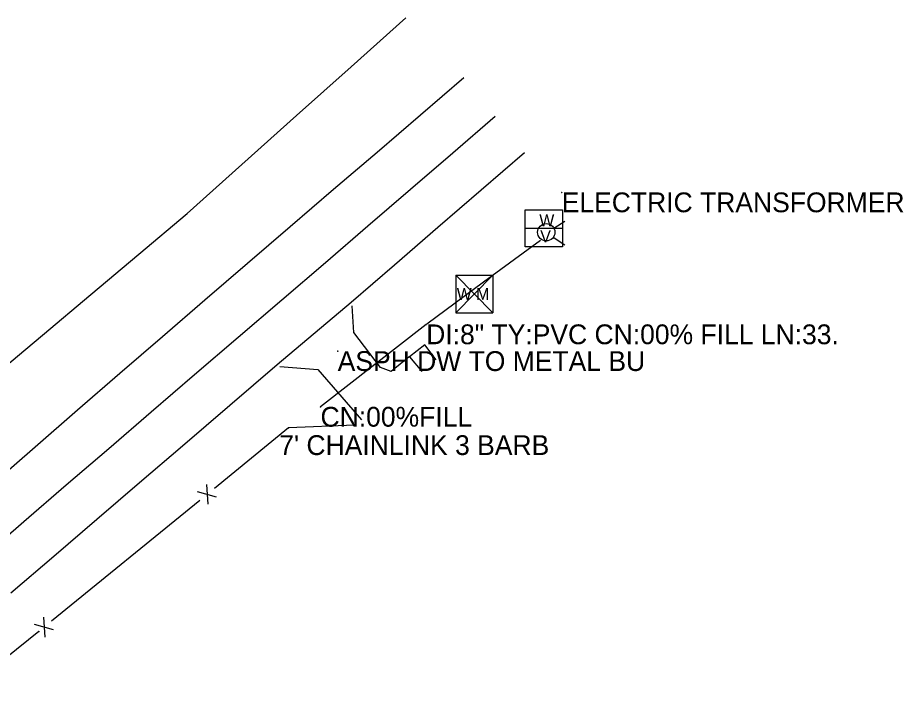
# Model space of a CAD drawing. Extents: x 1707085 to 1720058, y 548761 to 560063.
# Drawn here: x 1712693.8 to 1712917.4, y 549775.1 to 549943.4 of the extents above; entities that cross this region are included whole.
import ezdxf

# ---------------------------------------------------------------- set-up
doc = ezdxf.new("R2010")
doc.units = 0
for name, color, linetype in [('3', 7, 'Continuous'), ('R_Contours', 7, 'Continuous'), ('R_Water Annot', 7, 'Continuous'), ('S_DRG_PT_SYM', 7, 'Continuous'), ('S_DRIVEWAY', 7, 'Continuous'), ('S_EDGE_CONCRETE', 7, 'Continuous'), ('S_EDGE_PAVEMENT', 7, 'Continuous'), ('S_MISC_STRUCTURES_ANNOT', 7, 'Continuous'), ('S_MSC_PT_SYM', 7, 'Continuous'), ('S_PAVEMENT_CROWN', 7, 'Continuous'), ('S_SIDE_DRAIN_ANNOT', 7, 'Continuous'), ('S_SURVEY_TEXT_ANNOT', 7, 'Continuous')]:
    doc.layers.add(name, color=color, linetype=linetype)

msp = doc.modelspace()

# ---------------------------------------------------------------- linework, layer by layer
for points in [[(1712687.84, 549853.05), (1712700.01, 549863.27), (1712712.19, 549873.5), (1712724.37, 549883.72), (1712736.55, 549893.95), (1712750.36, 549906.32), (1712764.17, 549918.7), (1712777.99, 549931.07), (1712791.8, 549943.44)], [(1712825.79, 549887.17), (1712811.41, 549876.6), (1712797.03, 549866.03)]]:
    msp.add_lwpolyline(points)
at = {"layer": '3'}
msp.add_line((1712796.9, 549865.96), (1712770.22, 549845.13), dxfattribs=at)
at = {"layer": 'R_Contours'}
for p, q in [((1712778.87, 549840.55), (1712762.15, 549839.8)), ((1712741.39, 549825.52), (1712741.76, 549820.53)), ((1712743.98, 549822.35), (1712739.17, 549823.71)), ((1712700.24, 549791.98), (1712700.61, 549786.99)), ((1712702.83, 549788.81), (1712698.02, 549790.17))]:
    msp.add_line(p, q, dxfattribs=at)
for points in [[(1712778.87, 549840.55), (1712762.15, 549839.8)], [(1712762.15, 549839.8), (1712743.45, 549824.55)], [(1712739.71, 549821.5), (1712702.3, 549791.01)], [(1712699.09, 549788.39), (1712682.55, 549775.05)]]:
    msp.add_lwpolyline(points, dxfattribs=at)
at = {"layer": 'R_Water Annot'}
for p, q in [((1712821.91, 549894.93), (1712831.32, 549894.93)), ((1712821.91, 549885.52), (1712821.91, 549894.93)), ((1712831.32, 549894.93), (1712831.32, 549885.52)), ((1712829.12, 549890.3), (1712831.94, 549892.03)), ((1712821.91, 549890.24), (1712831.32, 549890.24)), ((1712828.99, 549887.99), (1712831.9, 549886.06)), ((1712831.32, 549885.52), (1712821.91, 549885.52)), ((1712804.42, 549878.41), (1712813.76, 549878.41)), ((1712804.42, 549878.41), (1712804.42, 549868.91)), ((1712804.42, 549878.41), (1712813.76, 549868.91)), ((1712813.76, 549878.41), (1712804.42, 549868.91)), ((1712813.76, 549878.41), (1712813.76, 549868.91)), ((1712804.42, 549868.91), (1712813.76, 549868.91))]:
    msp.add_line(p, q, dxfattribs=at)
msp.add_circle((1712827.21, 549889.24), 2.18, dxfattribs=at)
at = {"layer": 'S_DRG_PT_SYM'}
for points in [[(1712796.9, 549865.96), (1712796.9, 549866.01), (1712796.9, 549865.96), (1712796.85, 549865.96), (1712796.9, 549865.96), (1712796.9, 549865.91), (1712796.9, 549865.96), (1712796.95, 549865.96)], [(1712770.22, 549845.13), (1712770.22, 549845.18), (1712770.22, 549845.13), (1712770.17, 549845.13), (1712770.22, 549845.13), (1712770.22, 549845.08), (1712770.22, 549845.13), (1712770.27, 549845.13)]]:
    msp.add_lwpolyline(points, dxfattribs=at)
at = {"layer": 'S_DRIVEWAY'}
for points in [[(1712792.59, 549857.74), (1712788.04, 549854.08), (1712785.35, 549855.11), (1712778.67, 549863.91), (1712778.22, 549870.69)], [(1712759.92, 549855.36), (1712769.53, 549854.6), (1712780.56, 549841.85)]]:
    msp.add_lwpolyline(points, dxfattribs=at)
at = {"layer": 'S_EDGE_CONCRETE'}
msp.add_lwpolyline([(1712799.39, 549857.03), (1712796.55, 549860.79), (1712792.72, 549857.76), (1712795.77, 549854.04)], dxfattribs=at)
at = {"layer": 'S_EDGE_PAVEMENT'}
for points in [[(1712806.42, 549928.23), (1712795.45, 549918.82), (1712784.48, 549909.41), (1712773.51, 549900.01), (1712762.54, 549890.6), (1712751.79, 549881.34), (1712741.03, 549872.08), (1712730.28, 549862.81), (1712719.53, 549853.55), (1712708.83, 549844.26), (1712698.14, 549834.96), (1712687.44, 549825.67)], [(1712821.74, 549909.31), (1712810.79, 549899.87), (1712799.83, 549890.42), (1712788.88, 549880.97), (1712777.92, 549871.52), (1712759.29, 549855.72), (1712747.34, 549845.46), (1712735.4, 549835.21), (1712724.55, 549825.93), (1712713.71, 549816.65), (1712702.87, 549807.37), (1712692.02, 549798.1)]]:
    msp.add_lwpolyline(points, dxfattribs=at)
at = {"layer": 'S_MSC_PT_SYM'}
for points in [[(1712831.12, 549899.3), (1712831.12, 549899.35), (1712831.12, 549899.3), (1712831.07, 549899.3), (1712831.12, 549899.3), (1712831.12, 549899.25), (1712831.12, 549899.3), (1712831.17, 549899.3)], [(1712774.55, 549859.2), (1712774.55, 549859.25), (1712774.55, 549859.2), (1712774.5, 549859.2), (1712774.55, 549859.2), (1712774.55, 549859.15), (1712774.55, 549859.2), (1712774.6, 549859.2)], [(1712778.87, 549840.55), (1712778.87, 549840.6), (1712778.87, 549840.55), (1712778.82, 549840.55), (1712778.87, 549840.55), (1712778.87, 549840.5), (1712778.87, 549840.55), (1712778.92, 549840.55)], [(1712759.81, 549837.97), (1712759.81, 549838.02), (1712759.81, 549837.97), (1712759.76, 549837.97), (1712759.81, 549837.97), (1712759.81, 549837.92), (1712759.81, 549837.97), (1712759.86, 549837.97)], [(1712762.15, 549839.8), (1712762.15, 549839.85), (1712762.15, 549839.8), (1712762.1, 549839.8), (1712762.15, 549839.8), (1712762.15, 549839.75), (1712762.15, 549839.8), (1712762.2, 549839.8)], [(1712699.09, 549788.39), (1712699.09, 549788.44), (1712699.09, 549788.39), (1712699.04, 549788.39), (1712699.09, 549788.39), (1712699.09, 549788.34), (1712699.09, 549788.39), (1712699.14, 549788.39)]]:
    msp.add_lwpolyline(points, dxfattribs=at)
at = {"layer": 'S_PAVEMENT_CROWN'}
msp.add_lwpolyline([(1712814.34, 549918.45), (1712803.62, 549909.23), (1712792.9, 549900.01), (1712782.18, 549890.79), (1712771.47, 549881.56), (1712760.46, 549872.12), (1712749.45, 549862.68), (1712738.44, 549853.24), (1712727.43, 549843.81), (1712716.73, 549834.57), (1712706.02, 549825.34), (1712695.32, 549816.1), (1712684.62, 549806.87)], dxfattribs=at)

# ---------------------------------------------------------------- texts
at = {"layer": 'R_Water Annot'}
for s, p in [('W', (1712825.46, 549890.77)), ('V', (1712825.7, 549886.71)), ('W M', (1712804.62, 549872.17))]:
    msp.add_text(s, height=3, rotation=360, dxfattribs=at).set_placement(p)
at = {"layer": 'S_MISC_STRUCTURES_ANNOT'}
msp.add_text('ELECTRIC TRANSFORMER', height=5, dxfattribs=at).set_placement((1712831.12, 549894.3))
at = {"layer": 'S_SIDE_DRAIN_ANNOT'}
for s, p in [('DI:8" TY:PVC CN:00% FILL LN:33.', (1712796.9, 549860.96)), ('CN:00%FILL', (1712770.22, 549840.13))]:
    msp.add_text(s, height=5, dxfattribs=at).set_placement(p)
at = {"layer": 'S_SURVEY_TEXT_ANNOT'}
for s, p in [('ASPH DW TO METAL BU', (1712774.55, 549854.2)), ("7' CHAINLINK 3 BARB", (1712759.81, 549832.97))]:
    msp.add_text(s, height=5, dxfattribs=at).set_placement(p)

doc.saveas('drawing.dxf')
